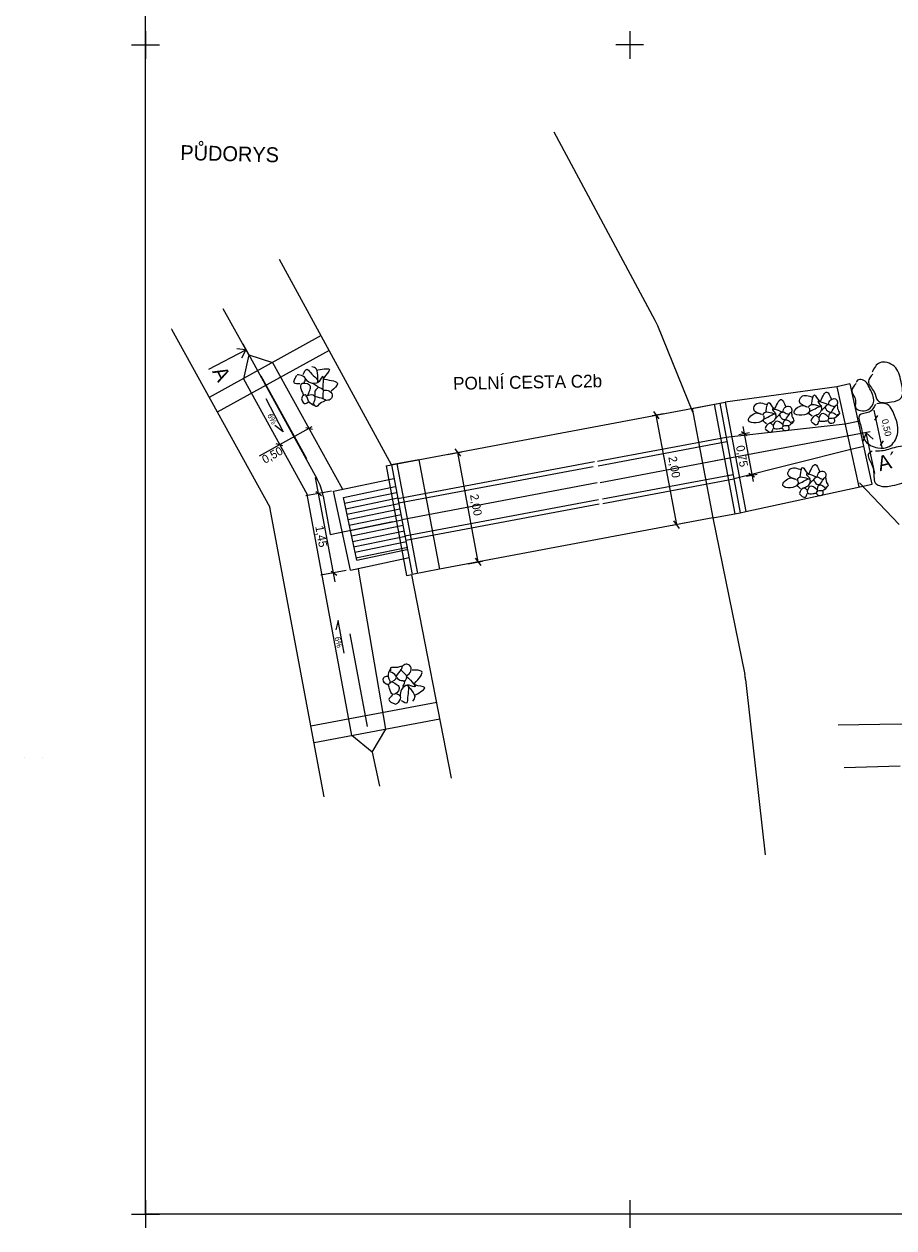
# Model space of a CAD drawing. Extents: x -463095.2 to -463031, y -1105061.3 to -1104976.3.
# Drawn here: x -463095.23 to -463063.97, y -1105061.31 to -1105018.06 of the extents above; entities that cross this region are included whole.
import ezdxf

# ---------------------------------------------------------------- set-up
doc = ezdxf.new("R2010")
doc.units = 0
for name, color, linetype in [('Implicitní', 7, 'Continuous'), ('Vrstva 14', 7, 'Continuous'), ('Vrstva 57', 7, 'Continuous')]:
    doc.layers.add(name, color=color, linetype=linetype)

msp = doc.modelspace()

# ---------------------------------------------------------------- linework, layer by layer
at = {"layer": 'Implicitní'}
for p, q in [((-463073.467, -1105018.311), (-463073.467, -1105019.311)), ((-463073.467, -1105018.311), (-463073.467, -1105019.311)), ((-463073.467, -1105018.311), (-463073.467, -1105019.311)), ((-463073.467, -1105018.311), (-463073.467, -1105019.311)), ((-463073.467, -1105018.311), (-463073.467, -1105019.311)), ((-463073.467, -1105018.311), (-463073.467, -1105019.311)), ((-463072.967, -1105018.811), (-463073.967, -1105018.811)), ((-463072.967, -1105018.811), (-463073.967, -1105018.811)), ((-463072.967, -1105018.811), (-463073.967, -1105018.811)), ((-463072.967, -1105018.811), (-463073.967, -1105018.811)), ((-463072.967, -1105018.811), (-463073.967, -1105018.811)), ((-463072.967, -1105018.811), (-463073.967, -1105018.811)), ((-463073.467, -1105060.311), (-463073.467, -1105061.311)), ((-463073.467, -1105060.311), (-463073.467, -1105061.311)), ((-463072.967, -1105060.811), (-463073.967, -1105060.811)), ((-463072.967, -1105060.811), (-463073.967, -1105060.811))]:
    msp.add_line(p, q, dxfattribs=at)
at = {"layer": 'Vrstva 14'}
for p, q in [((-463090.867, -1105018.311), (-463090.867, -1105019.311)), ((-463090.867, -1105018.311), (-463090.867, -1105019.311)), ((-463090.867, -1105018.311), (-463090.867, -1105019.311)), ((-463090.867, -1105018.312), (-463090.867, -1105019.312)), ((-463091.367, -1105018.811), (-463090.367, -1105018.811)), ((-463091.367, -1105018.811), (-463090.367, -1105018.811)), ((-463091.367, -1105018.811), (-463090.367, -1105018.811)), ((-463091.367, -1105018.812), (-463090.367, -1105018.812)), ((-463072.552, -1105028.71), (-463076.182, -1105021.944)), ((-463082.033, -1105033.9), (-463086.05, -1105026.519)), ((-463087.151, -1105029.945), (-463088.076, -1105028.286)), ((-463084.553, -1105029.255), (-463088.579, -1105031.479)), ((-463071.202, -1105032.001), (-463072.461, -1105028.903)), ((-463087.369, -1105029.55), (-463084.698, -1105034.406)), ((-463084.262, -1105029.782), (-463088.288, -1105032.006)), ((-463087.263, -1105029.762), (-463087.413, -1105030.063)), ((-463086.725, -1105030.7), (-463085.088, -1105033.663)), ((-463065.552, -1105030.991), (-463066.021, -1105031.094)), ((-463065.552, -1105030.991), (-463064.766, -1105034.586)), ((-463066.021, -1105031.094), (-463070.038, -1105031.647)), ((-463066.021, -1105031.094), (-463065.235, -1105034.689)), ((-463082.225, -1105033.937), (-463070.224, -1105031.682)), ((-463071.217, -1105031.868), (-463070.234, -1105031.684)), ((-463071.217, -1105031.868), (-463070.478, -1105035.8)), ((-463070.431, -1105031.721), (-463069.692, -1105035.652)), ((-463070.234, -1105031.684), (-463070.038, -1105031.647)), ((-463070.234, -1105031.684), (-463069.495, -1105035.615)), ((-463070.038, -1105031.647), (-463069.299, -1105035.578)), ((-463072.249, -1105032.062), (-463072.664, -1105032.14)), ((-463072.618, -1105031.979), (-463072.415, -1105032.246)), ((-463071.778, -1105036.044), (-463072.516, -1105032.113)), ((-463064.389, -1105033.275), (-463064.683, -1105031.931)), ((-463064.559, -1105032.118), (-463064.665, -1105032.285)), ((-463086.773, -1105033.571), (-463084.878, -1105032.524)), ((-463084.872, -1105032.63), (-463085.111, -1105032.563)), ((-463065.721, -1105032.436), (-463070.007, -1105032.91)), ((-463069.54, -1105032.808), (-463069.158, -1105032.738)), ((-463069.241, -1105032.851), (-463069.444, -1105032.709)), ((-463069.399, -1105032.515), (-463069.033, -1105034.5)), ((-463065.261, -1105032.336), (-463065.73, -1105032.438)), ((-463085.934, -1105033.21), (-463086.172, -1105033.143)), ((-463074.619, -1105033.769), (-463070.005, -1105032.902)), ((-463074.599, -1105033.928), (-463069.976, -1105033.06)), ((-463064.972, -1105032.749), (-463064.721, -1105032.973)), ((-463064.364, -1105033.031), (-463064.47, -1105033.199)), ((-463080.013, -1105033.522), (-463079.5, -1105033.425)), ((-463079.749, -1105033.319), (-463079.546, -1105033.587)), ((-463078.909, -1105037.384), (-463079.648, -1105033.453)), ((-463065.522, -1105033.345), (-463069.708, -1105034.393)), ((-463065.053, -1105033.242), (-463065.522, -1105033.345)), ((-463082.224, -1105033.937), (-463082.028, -1105033.9)), ((-463082.224, -1105033.937), (-463081.486, -1105037.868)), ((-463081.045, -1105033.716), (-463082.028, -1105033.9)), ((-463082.028, -1105033.9), (-463081.289, -1105037.832)), ((-463081.831, -1105033.863), (-463081.092, -1105037.795)), ((-463074.736, -1105033.792), (-463081.799, -1105035.119)), ((-463074.776, -1105033.962), (-463081.769, -1105035.276)), ((-463081.045, -1105033.716), (-463080.306, -1105037.647)), ((-463074.523, -1105034.525), (-463069.865, -1105033.649)), ((-463084.055, -1105038.094), (-463084.759, -1105034.351)), ((-463084.111, -1105034.843), (-463081.945, -1105034.381)), ((-463074.45, -1105035.122), (-463069.754, -1105034.239)), ((-463074.43, -1105035.281), (-463069.725, -1105034.396)), ((-463069.265, -1105034.303), (-463068.883, -1105034.233)), ((-463068.981, -1105034.344), (-463069.184, -1105034.202)), ((-463084.188, -1105034.842), (-463085.108, -1105035.015)), ((-463084.749, -1105034.856), (-463084.546, -1105034.997)), ((-463083.507, -1105037.679), (-463084.111, -1105034.843)), ((-463083.754, -1105035.073), (-463081.891, -1105034.676)), ((-463081.846, -1105034.903), (-463083.711, -1105035.287)), ((-463074.631, -1105034.545), (-463081.658, -1105035.866)), ((-463069.299, -1105035.578), (-463064.76, -1105034.585)), ((-463063.779, -1105036.043), (-463065.206, -1105034.538)), ((-463083.275, -1105037.323), (-463083.754, -1105035.073)), ((-463081.805, -1105035.099), (-463083.67, -1105035.483)), ((-463081.765, -1105035.295), (-463083.63, -1105035.678)), ((-463074.589, -1105035.148), (-463081.548, -1105036.456)), ((-463074.56, -1105035.305), (-463081.518, -1105036.613)), ((-463084.447, -1105045.822), (-463086.403, -1105035.42)), ((-463081.725, -1105035.49), (-463083.59, -1105035.874)), ((-463081.684, -1105035.686), (-463083.549, -1105036.07)), ((-463070.478, -1105035.8), (-463069.495, -1105035.615)), ((-463069.495, -1105035.615), (-463069.299, -1105035.578)), ((-463081.644, -1105035.882), (-463083.509, -1105036.266)), ((-463081.604, -1105036.078), (-463083.469, -1105036.462)), ((-463070.478, -1105035.8), (-463080.306, -1105037.647)), ((-463071.51, -1105035.993), (-463071.925, -1105036.071)), ((-463071.676, -1105036.177), (-463071.879, -1105035.91)), ((-463070.478, -1105035.8), (-463069.331, -1105041.43)), ((-463081.563, -1105036.274), (-463083.428, -1105036.658)), ((-463081.523, -1105036.47), (-463083.388, -1105036.854)), ((-463081.483, -1105036.666), (-463083.348, -1105037.05)), ((-463081.442, -1105036.862), (-463083.307, -1105037.246)), ((-463083.275, -1105037.323), (-463081.472, -1105036.939)), ((-463083.507, -1105037.679), (-463081.39, -1105037.228)), ((-463079.274, -1105037.453), (-463078.761, -1105037.356)), ((-463078.807, -1105037.518), (-463079.01, -1105037.251)), ((-463083.653, -1105037.692), (-463084.573, -1105037.865)), ((-463084.2, -1105037.716), (-463083.996, -1105037.857)), ((-463081.486, -1105037.868), (-463081.289, -1105037.832)), ((-463081.307, -1105037.845), (-463079.886, -1105045.155)), ((-463080.306, -1105037.647), (-463081.289, -1105037.832)), ((-463082.886, -1105043.301), (-463083.512, -1105039.973)), ((-463069.303, -1105041.609), (-463068.828, -1105045.882)), ((-463080.403, -1105042.44), (-463084.923, -1105043.289)), ((-463080.291, -1105043.031), (-463084.812, -1105043.881)), ((-463082.727, -1105044.219), (-463082.459, -1105045.444)), ((-463095.232, -1105044.423), (-463095.232, -1105044.423)), ((-463094.581, -1105044.423), (-463094.581, -1105044.423)), ((-463063.745, -1105044.725), (-463065.755, -1105044.785)), ((-463068.828, -1105045.882), (-463068.604, -1105047.901)), ((-463090.867, -1105060.311), (-463090.867, -1105061.311)), ((-463091.367, -1105060.811), (-463090.367, -1105060.811))]:
    msp.add_line(p, q, dxfattribs=at)
msp.add_lwpolyline([(-463090.867, -1105060.811), (-463090.867, -1104976.812), (-463031.467, -1104976.812), (-463031.467, -1105060.811)], close=True, dxfattribs=at)
for points in [[(-463089.924, -1105029.024), (-463089.939, -1105029.018), (-463086.403, -1105035.42)], [(-463088.587, -1105030.454), (-463087.263, -1105029.762), (-463087.588, -1105029.728)], [(-463087.151, -1105029.945), (-463087.35, -1105030.805), (-463085.055, -1105034.965)], [(-463087.151, -1105029.945), (-463086.304, -1105030.221), (-463083.789, -1105034.775)], [(-463086.544, -1105031.518), (-463085.919, -1105032.714), (-463086.223, -1105032.485)], [(-463070.387, -1105033.745), (-463064.826, -1105032.694)], [(-463064.653, -1105034.208), (-463064.972, -1105032.749), (-463065.091, -1105033.053)], [(-463082.727, -1105044.219), (-463083.454, -1105043.624), (-463085.055, -1105034.965)], [(-463084.481, -1105035.017), (-463084.235, -1105036.393), (-463081.986, -1105035.931)], [(-463082.727, -1105044.219), (-463082.231, -1105043.396), (-463083.216, -1105037.642)], [(-463083.727, -1105040.656), (-463083.944, -1105039.484), (-463084.028, -1105039.822)], [(-463065.972, -1105043.24), (-463063.741, -1105043.201), (-463054.531, -1105043.611)]]:
    msp.add_lwpolyline(points, dxfattribs=at)
for centre, start, end in [((-463074.314, -1105029.656), 22.1223, 28.2143), ((-463086.45, -1105035.37), 10.1509, 28.8207), ((-463071.291, -1105041.83), 6.3401, 11.5166)]:
    msp.add_arc(centre, 2, start, end, dxfattribs=at)
for points in [[(-463085.2, -1105030.652), (-463085.074, -1105030.462), (-463084.943, -1105030.579), (-463084.68, -1105030.932), (-463084.939, -1105030.954), (-463085.12, -1105030.797)], [(-463084.499, -1105031.209), (-463084.519, -1105030.735), (-463084.653, -1105030.931), (-463084.726, -1105030.459), (-463084.893, -1105030.376)], [(-463084.672, -1105030.482), (-463084.253, -1105030.481), (-463084.449, -1105030.763), (-463084.478, -1105030.834)], [(-463064.736, -1105030.638), (-463064.888, -1105030.896), (-463064.687, -1105031.276), (-463064.553, -1105031.583), (-463064.063, -1105031.637), (-463063.715, -1105031.49), (-463063.715, -1105030.91), (-463063.96, -1105030.352), (-463064.482, -1105030.227), (-463064.759, -1105030.566)], [(-463085.324, -1105030.99), (-463085.516, -1105030.961), (-463085.433, -1105030.673)], [(-463085.172, -1105030.947), (-463085.124, -1105030.814), (-463085.325, -1105030.669), (-463085.422, -1105030.668)], [(-463085.029, -1105031.38), (-463084.979, -1105031.028), (-463085.285, -1105031.01), (-463085.245, -1105031.257), (-463085.181, -1105031.398)], [(-463084.831, -1105031.001), (-463084.663, -1105031.112), (-463084.75, -1105031.199), (-463084.783, -1105031.407)], [(-463084.436, -1105030.822), (-463083.967, -1105030.986), (-463084.201, -1105031.248)], [(-463065.328, -1105030.978), (-463065.489, -1105031.223), (-463065.351, -1105031.576), (-463065.351, -1105031.825), (-463064.909, -1105031.919), (-463064.7, -1105031.611), (-463064.833, -1105031.165), (-463065.159, -1105030.826), (-463065.309, -1105030.885), (-463065.325, -1105030.941)], [(-463084.769, -1105031.776), (-463085.008, -1105031.611), (-463085.134, -1105031.384), (-463085.242, -1105031.457), (-463085.154, -1105031.691), (-463085.007, -1105031.638)], [(-463085.117, -1105031.415), (-463084.794, -1105031.413), (-463084.816, -1105031.64), (-463084.852, -1105031.7)], [(-463084.782, -1105031.434), (-463084.401, -1105031.586), (-463084.597, -1105031.694), (-463084.741, -1105031.802), (-463084.813, -1105031.72)], [(-463084.692, -1105031.091), (-463084.477, -1105031.224), (-463084.49, -1105031.325), (-463084.497, -1105031.532)], [(-463084.487, -1105031.218), (-463084.25, -1105031.247), (-463084.158, -1105031.438), (-463084.232, -1105031.548), (-463084.409, -1105031.579)], [(-463067.074, -1105031.818), (-463067.37, -1105031.626), (-463067.297, -1105031.451), (-463066.879, -1105031.47)], [(-463066.925, -1105031.707), (-463066.83, -1105031.385), (-463066.659, -1105031.599), (-463066.611, -1105031.638)], [(-463066.61, -1105031.603), (-463066.378, -1105031.281), (-463066.23, -1105031.52)], [(-463068.715, -1105032.088), (-463069.011, -1105031.895), (-463068.938, -1105031.721), (-463068.519, -1105031.74)], [(-463067.969, -1105032.01), (-463068.336, -1105031.917), (-463068.217, -1105032.064), (-463068.595, -1105032.013), (-463068.698, -1105032.122)], [(-463068.566, -1105031.977), (-463068.471, -1105031.654), (-463068.299, -1105031.869), (-463068.251, -1105031.908)], [(-463068.251, -1105031.873), (-463068.018, -1105031.551), (-463067.871, -1105031.79)], [(-463067.959, -1105032.003), (-463067.883, -1105031.827), (-463067.715, -1105031.8), (-463067.648, -1105031.882), (-463067.664, -1105032.025)], [(-463067.018, -1105031.853), (-463067.007, -1105031.978), (-463067.553, -1105032.034), (-463067.262, -1105031.762), (-463067.108, -1105031.809)], [(-463066.328, -1105031.74), (-463066.696, -1105031.647), (-463066.577, -1105031.794), (-463066.955, -1105031.743), (-463067.057, -1105031.852)], [(-463066.915, -1105032.15), (-463067.032, -1105032.01), (-463066.913, -1105031.936), (-463066.582, -1105031.815), (-463066.624, -1105032.019), (-463066.785, -1105032.122)], [(-463066.563, -1105031.947), (-463066.44, -1105031.843), (-463066.393, -1105031.929), (-463066.241, -1105032.003)], [(-463066.462, -1105031.861), (-463066.312, -1105031.726), (-463066.237, -1105031.759), (-463066.08, -1105031.812)], [(-463066.318, -1105031.733), (-463066.242, -1105031.557), (-463066.074, -1105031.53), (-463066.007, -1105031.612), (-463066.024, -1105031.755)], [(-463066.22, -1105032.008), (-463066.016, -1105031.75), (-463065.978, -1105031.925), (-463065.929, -1105032.06), (-463066.008, -1105032.097)], [(-463064.638, -1105031.731), (-463064.865, -1105031.999), (-463065.208, -1105032.115), (-463065.159, -1105032.507), (-463064.999, -1105033.047), (-463064.553, -1105033.288), (-463064.143, -1105033.239), (-463063.848, -1105032.806), (-463063.947, -1105032.128), (-463064.259, -1105031.704), (-463064.589, -1105031.704)], [(-463068.658, -1105032.123), (-463068.647, -1105032.248), (-463069.193, -1105032.304), (-463068.902, -1105032.032), (-463068.748, -1105032.079)], [(-463068.555, -1105032.42), (-463068.673, -1105032.28), (-463068.553, -1105032.206), (-463068.223, -1105032.085), (-463068.265, -1105032.289), (-463068.426, -1105032.391)], [(-463067.958, -1105032.455), (-463068.217, -1105032.336), (-463068.3, -1105032.567), (-463068.102, -1105032.592), (-463067.979, -1105032.575)], [(-463068.204, -1105032.217), (-463068.08, -1105032.113), (-463068.034, -1105032.199), (-463067.882, -1105032.272)], [(-463068.103, -1105032.131), (-463067.952, -1105031.996), (-463067.878, -1105032.029), (-463067.72, -1105032.082)], [(-463067.952, -1105032.53), (-463067.88, -1105032.282), (-463067.711, -1105032.351), (-463067.672, -1105032.392)], [(-463067.861, -1105032.278), (-463067.657, -1105032.02), (-463067.619, -1105032.195), (-463067.569, -1105032.33), (-463067.648, -1105032.367)], [(-463066.682, -1105032.196), (-463066.774, -1105032.129), (-463066.931, -1105032.25), (-463066.954, -1105032.324)], [(-463066.318, -1105032.185), (-463066.576, -1105032.066), (-463066.66, -1105032.297), (-463066.461, -1105032.323), (-463066.339, -1105032.306)], [(-463065.955, -1105032.076), (-463066.136, -1105032.222), (-463066.339, -1105032.266), (-463066.308, -1105032.366), (-463066.108, -1105032.352), (-463066.115, -1105032.227)], [(-463066.311, -1105032.26), (-463066.239, -1105032.012), (-463066.07, -1105032.081), (-463066.032, -1105032.122)], [(-463068.323, -1105032.466), (-463068.414, -1105032.399), (-463068.571, -1105032.52), (-463068.594, -1105032.594)], [(-463068.325, -1105032.592), (-463068.39, -1105032.733), (-463068.592, -1105032.603)], [(-463067.596, -1105032.346), (-463067.776, -1105032.492), (-463067.98, -1105032.536), (-463067.948, -1105032.636), (-463067.748, -1105032.622), (-463067.756, -1105032.497)], [(-463066.684, -1105032.322), (-463066.75, -1105032.463), (-463066.952, -1105032.333)], [(-463064.754, -1105033.408), (-463064.883, -1105033.502), (-463064.78, -1105033.859), (-463064.691, -1105034.323), (-463064.642, -1105034.542), (-463064.491, -1105034.644), (-463064.031, -1105034.644), (-463063.394, -1105034.394), (-463063.131, -1105033.993), (-463063.131, -1105033.654), (-463063.389, -1105033.284), (-463063.969, -1105033.284), (-463064.486, -1105033.404), (-463064.629, -1105033.404)], [(-463067.488, -1105034.422), (-463067.784, -1105034.23), (-463067.71, -1105034.055), (-463067.292, -1105034.075)], [(-463067.338, -1105034.311), (-463067.243, -1105033.989), (-463067.072, -1105034.203), (-463067.024, -1105034.242)], [(-463067.024, -1105034.208), (-463066.791, -1105033.885), (-463066.644, -1105034.125)], [(-463067.431, -1105034.457), (-463067.42, -1105034.583), (-463067.966, -1105034.638), (-463067.675, -1105034.367), (-463067.521, -1105034.413)], [(-463066.741, -1105034.344), (-463067.109, -1105034.251), (-463066.99, -1105034.398), (-463067.368, -1105034.347), (-463067.47, -1105034.456)], [(-463067.328, -1105034.754), (-463067.446, -1105034.614), (-463067.326, -1105034.541), (-463066.995, -1105034.419), (-463067.037, -1105034.623), (-463067.198, -1105034.726)], [(-463066.976, -1105034.551), (-463066.853, -1105034.447), (-463066.806, -1105034.534), (-463066.655, -1105034.607)], [(-463066.875, -1105034.465), (-463066.725, -1105034.331), (-463066.65, -1105034.364), (-463066.493, -1105034.416)], [(-463066.732, -1105034.337), (-463066.655, -1105034.161), (-463066.488, -1105034.135), (-463066.42, -1105034.217), (-463066.437, -1105034.359)], [(-463066.634, -1105034.612), (-463066.43, -1105034.355), (-463066.391, -1105034.53), (-463066.342, -1105034.665), (-463066.421, -1105034.701)], [(-463067.095, -1105034.8), (-463067.187, -1105034.733), (-463067.344, -1105034.854), (-463067.367, -1105034.928)], [(-463066.731, -1105034.789), (-463066.989, -1105034.67), (-463067.073, -1105034.901), (-463066.874, -1105034.927), (-463066.752, -1105034.91)], [(-463066.368, -1105034.68), (-463066.549, -1105034.826), (-463066.752, -1105034.871), (-463066.721, -1105034.97), (-463066.521, -1105034.956), (-463066.528, -1105034.831)], [(-463066.724, -1105034.864), (-463066.652, -1105034.616), (-463066.483, -1105034.686), (-463066.445, -1105034.726)], [(-463067.097, -1105034.926), (-463067.163, -1105035.067), (-463067.365, -1105034.937)], [(-463082.063, -1105041.225), (-463082.143, -1105041.505), (-463082.095, -1105041.76), (-463082.225, -1105041.773), (-463082.306, -1105041.536), (-463082.159, -1105041.484)], [(-463082.102, -1105041.725), (-463081.851, -1105041.521), (-463082.014, -1105041.361), (-463082.079, -1105041.336)], [(-463081.856, -1105041.498), (-463081.659, -1105041.137), (-463081.879, -1105041.179), (-463082.058, -1105041.188), (-463082.062, -1105041.296)], [(-463081.569, -1105041.704), (-463081.487, -1105041.465), (-463081.561, -1105041.396), (-463081.698, -1105041.24)], [(-463081.491, -1105041.476), (-463081.327, -1105041.303), (-463081.378, -1105041.096), (-463081.505, -1105041.059), (-463081.661, -1105041.148)], [(-463081.2, -1105041.749), (-463080.942, -1105041.324), (-463081.29, -1105041.271)], [(-463082.012, -1105041.696), (-463081.749, -1105041.936), (-463081.974, -1105042.145), (-463082.1, -1105041.928), (-463082.141, -1105041.779)], [(-463081.618, -1105041.862), (-463081.559, -1105041.67), (-463081.681, -1105041.658), (-463081.839, -1105041.519)], [(-463081.68, -1105042.366), (-463081.462, -1105042.433), (-463081.436, -1105042.259), (-463081.457, -1105041.82), (-463081.672, -1105041.968), (-463081.711, -1105042.203)], [(-463081.495, -1105041.491), (-463081.208, -1105041.868), (-463081.436, -1105041.803), (-463081.192, -1105042.213), (-463081.268, -1105042.384)], [(-463081.165, -1105042.162), (-463080.841, -1105041.895), (-463081.172, -1105041.803), (-463081.239, -1105041.767)], [(-463081.991, -1105042.185), (-463082.121, -1105042.329), (-463081.873, -1105042.498)], [(-463081.846, -1105042.121), (-463081.725, -1105042.194), (-463081.788, -1105042.433), (-463081.861, -1105042.496)]]:
    msp.add_spline(points, degree=3, dxfattribs=at)

# ---------------------------------------------------------------- texts
for s, height, rotation, p in [('PŮDORYS', 0.536, 358.5898, (-463089.622, -1105022.942)), ('A', 0.536, 297.5844, (-463088.481, -1105030.541)), ('0,50', 0.24, 282.3388, (-463064.419, -1105032.279)), ('0,50', 0.3, 28.9139, (-463086.579, -1105033.864)), ('2,00', 0.3, 280.6452, (-463072.081, -1105033.619)), ('0,75', 0.3, 280.4302, (-463069.648, -1105033.226)), ('A´', 0.536, 14.398, (-463064.48, -1105034.127)), ('2,00', 0.3, 280.6452, (-463079.208, -1105034.979)), ('1,45', 0.3, 280.6452, (-463084.769, -1105036.111))]:
    msp.add_text(s, height=height, rotation=rotation, dxfattribs=at).set_placement(p)
at = {"layer": 'Vrstva 57'}
for s, height, rotation, p in [('POLNÍ CESTA C2b', 0.459, 0.9997, (-463079.81, -1105031.201)), ('6%', 0.204, 297.5844, (-463086.499, -1105032.12)), ('6%', 0.204, 283.5402, (-463084.077, -1105040.099))]:
    msp.add_text(s, height=height, rotation=rotation, dxfattribs=at).set_placement(p)

doc.saveas('drawing.dxf')
